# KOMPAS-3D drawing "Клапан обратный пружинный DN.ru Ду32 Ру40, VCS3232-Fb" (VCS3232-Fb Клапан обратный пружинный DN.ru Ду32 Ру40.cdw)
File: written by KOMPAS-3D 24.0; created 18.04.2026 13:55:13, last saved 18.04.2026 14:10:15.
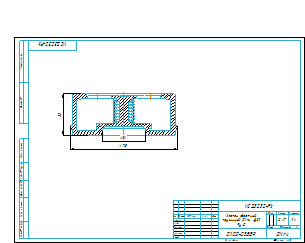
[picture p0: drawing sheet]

Document properties: c3d_UniqueCompID: 071bd168-1a06-425c-849c-e99e84a96128; Наименование: Деталь; Автор: 712; Класс точности: c; Знак неуказанной шероховатости: Шероховатость не задана; Рассекать на разрезах: Да; c3d_UniqueCompID: 071bd168-1a06-425c-849c-e99e84a96128; Наименование: Деталь; Автор: 712; Класс точности: c; Знак неуказанной шероховатости: Шероховатость не задана; Рассекать на разрезах: Да; c3d_UniqueCompID: 071bd168-1a06-425c-849c-e99e84a96128; Наименование: Деталь; Автор: 712; Класс точности: c; Знак неуказанной шероховатости: Шероховатость не задана; Рассекать на разрезах: Да; c3d_UniqueCompID: 071bd168-1a06-425c-849c-e99e84a96128; Наименование: Деталь; Автор: 712; Класс точности: c; Знак неуказанной шероховатости: Шероховатость не задана; Рассекать на разрезах: Да; Автор: 712; Форматы листов документа: A3; Полное имя файла: VCS3232-Fb Клапан обратный пружинный DN.ru Ду32 Ру40.m3d; Масса: 0.47; Наименование: Клапан обратный пружинный DN.ru Ду32 Ру40; Количество листов документа: 1; Примечание: D100-03889

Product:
- Component: Пружина 1086-0796 ГОСТ 18793-80  | qty 1  | additional columns: 3953604318-4147491677-0; Деталь; Пользователь Windows; c; Шероховатость не задана; Да; Сталь 10  ГОСТ 1050-88; source file: Деталь_1.m3d
- Body: Тело 1  | qty 1
    Масса: 0.345088
- Part/product: Клапан обратный пружинный DN.ru Ду32 Ру40  | designation VCS3232-Fb
    Масса: 0.47
    Раздел спецификации: Прочие изделия
    Примечание: D100-03889
    additional columns: 071bd168-1a06-425c-849c-e99e84a96128; Деталь; 712; c; Шероховатость не задана; Да

Views: Вид 1, Местный разрез 1, Спереди
Referenced files in C:\Users\712\Desktop\Новая папка (4)\: VCS3232-Fb Клапан обратный пружинный DN.ru Ду15 Ру40.m3d, VCS3232-Fb Клапан обратный пружинный DN.ru Ду32 Ру40.m3d, VCS3232-Fb Клапан обратный пружинный DN.ru Ду15 Ру40.cdw
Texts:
  VCS3232-Fb
  Клапан обратный
  пружинный DN.ru Ду32
  Ру40
  Клапан обратный пружинный DN.ru Ду32 Ру40
  VCS3232-Fb Клапан обратный пружинный DN.ru Ду32 Ру40
Dimensions and other numbers on the sheet: 0; 3; 2; 4; 78; 31; 30; 2:1; 1; 0,47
